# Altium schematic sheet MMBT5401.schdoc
size 127 x 101 mm
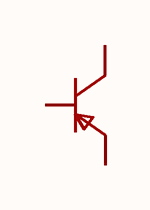
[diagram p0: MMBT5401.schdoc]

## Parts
Q?  mmbt5401(range:200-300)  [SOT-23-3_L2.9-W1.3-P1.90-LS2.4-BR]  (value not drawn)

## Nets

Not connected (* = marked no-connect by the designer): Q? 1(B) 2(E) 3(C)

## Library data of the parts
Q? = mmbt5401(range:200-300): 晶体管类型:PNP;集电极电流(Ic):600mA;集射极击穿电压(Vceo):150V;耗散功率(Pd):300mW;直流电流增益(hFE):300;; Manufacturer: CJ(江苏长电/长晶); AddInBom: yes; ModelId: c62791f0466c4ae2a892c056b845b0ca; ModelName: SOT-23-3P_L2.9-W1.3-H1.0-LS2.4-P0.95; ModelTransform: 98.425,114.173,0,180,0,0,0.0005,-0.0005,0; type: PNP; Current - Collector(Ic): 600mA; Collector - Emitter Voltage VCEO: 150V; Pd - Power Dissipation: 300mW; DC Current Gain: 300; Transition frequency(fT): 100MHz; Current - Collector Cutoff: 100nA; Vce Saturation(VCE(sat)): 500mV; Emitter-Base Voltage(Vebo): 5V; Number: 1个PNP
